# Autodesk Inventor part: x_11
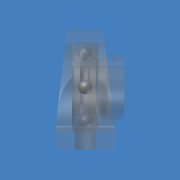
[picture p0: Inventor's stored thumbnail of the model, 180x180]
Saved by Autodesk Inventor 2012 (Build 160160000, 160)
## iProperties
Company: CAD-Verlag
Shininess: 64.0
Length Units: 11269
Angle Units: 11279
Time Units: 11290
Mass Units: 11283
Length Display Precision: 3
Angle Display Precision: 2
Compacted: True
Part Number: x_11
Document SubType Name: Modeling
Created: 2004-09
Material: Standard
Designer: Greiling
Manufacturer: Standard
Standards Organization: Custom
Density: 1 g/cm^3
Density: 0.0
Volumn: 0.0
Area: 0.0
PropertySet Name: Model Information
Control State: 0
Master: False
Checked Out: False
Author: Jürgen Kronas
Übersetzungsnorm: STEP AP214CD
Dateiname: w2c22665.stp
Vorprozessor: ACIS
Postprozessor: Build: 081d, Release: 8 SP1 - Date: Tue 01/26/2004
Gesendete Einheiten: MILLIMETERS
Unbestimmtheit: 1e-06
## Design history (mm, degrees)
feature "Basis1"
node "Volumenkörper1"
node "Volumenkörpern"
node "Oberflächenkörpern"
